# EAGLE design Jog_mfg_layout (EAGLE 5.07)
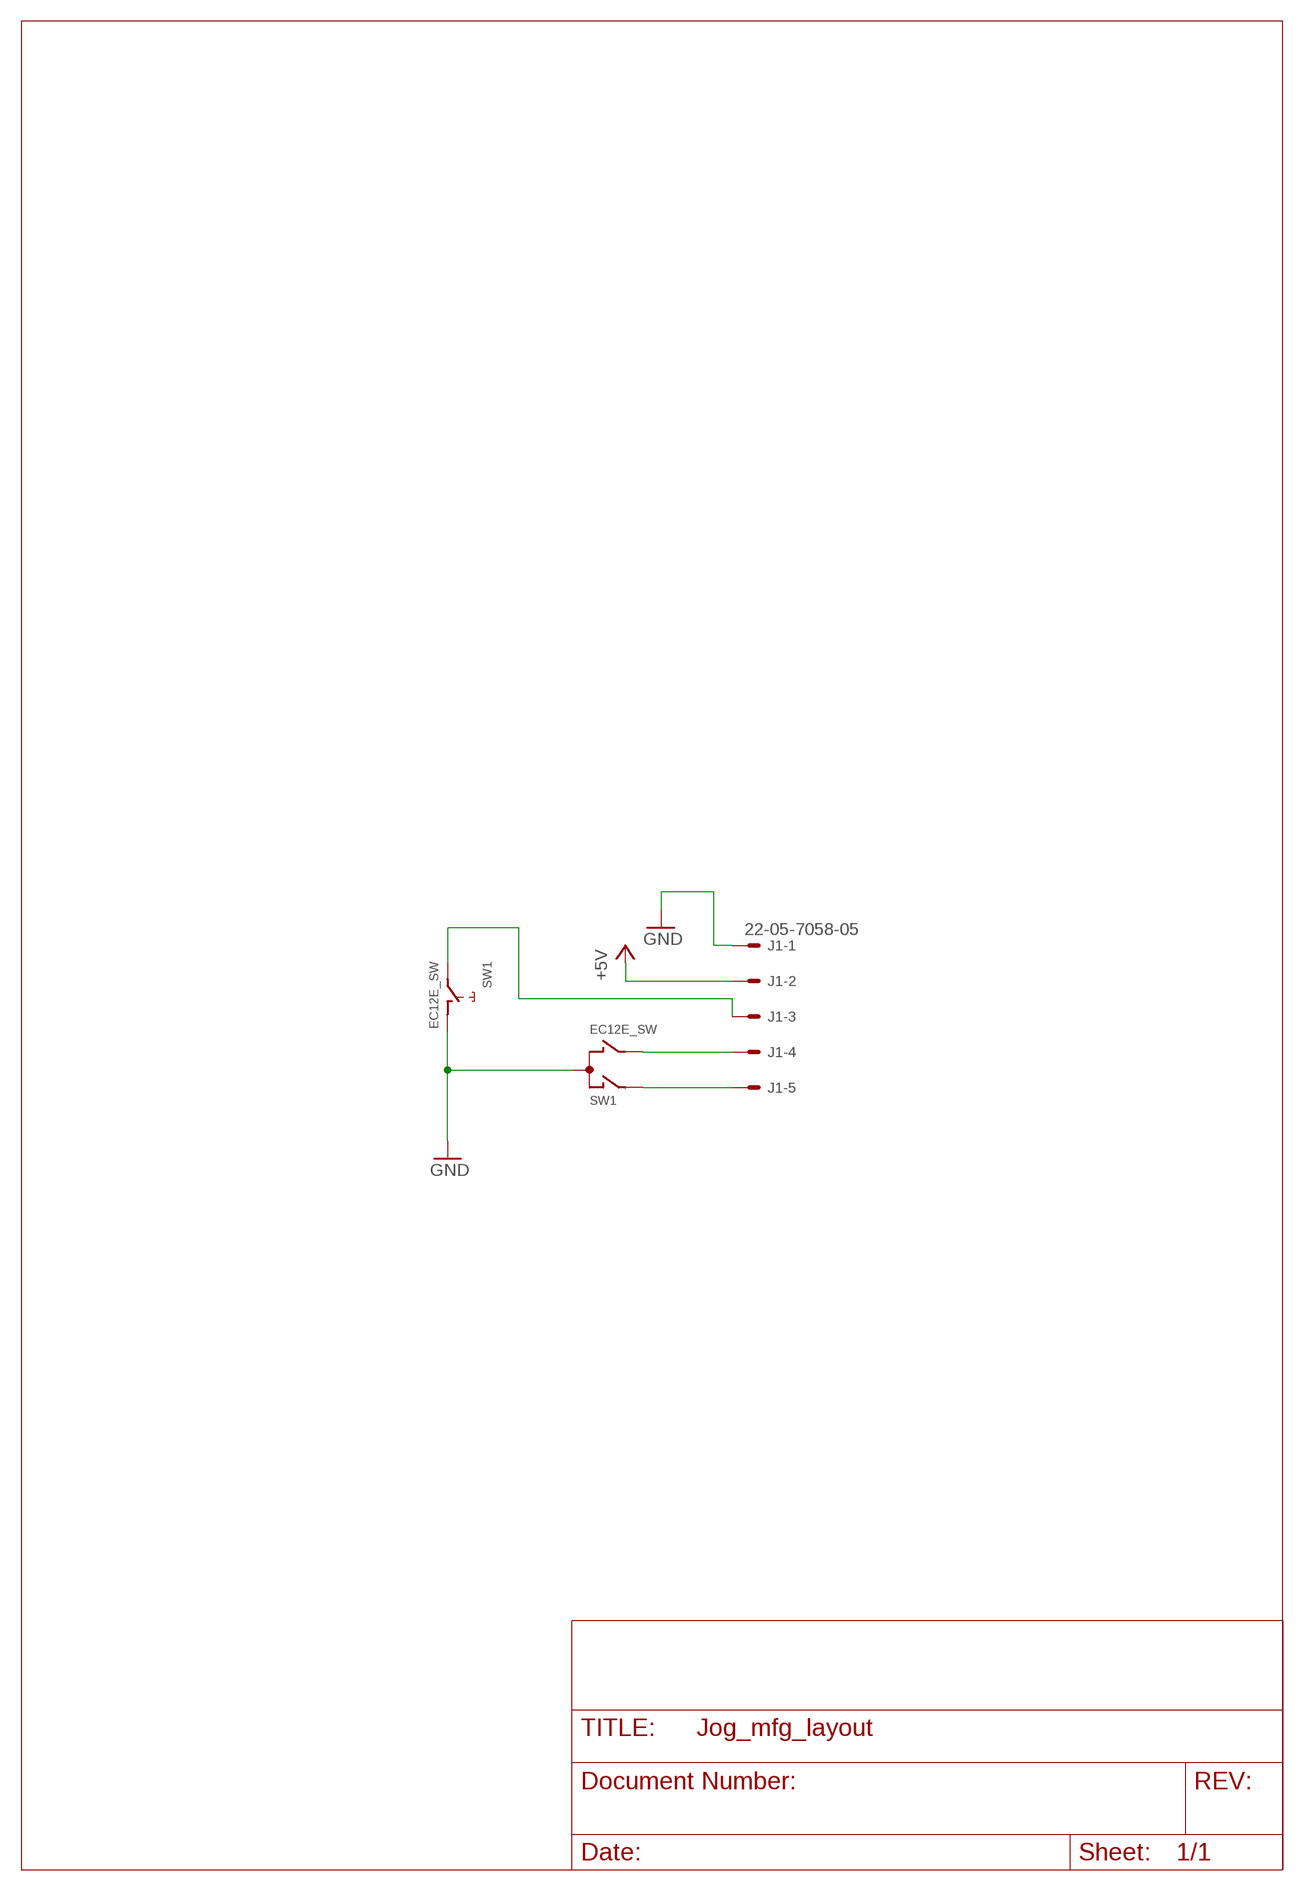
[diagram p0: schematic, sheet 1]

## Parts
J1  22-05-7058-05  [7395-05]
SW1  EC12E_SW  [ALPS_EC12E_SW]

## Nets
+5V: J1.2
GND: J1.1 SW1.C SW1.D
N$1: J1.5 SW1.A
N$2: J1.4 SW1.B
N$3: J1.3 SW1.E
Unconnected: SW1.GND1(G) SW1.GND2(G)

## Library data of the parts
J1 = con-molex:22-?-05: CONNECTOR wire to board 2.54 mm (.1 inch) pitch header
SW1 = switch-alps:EC12E_SW: ALPS rotary Encoder EC12E series with switch

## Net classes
0 default: width 1.27 mm, clearance 0.889 mm

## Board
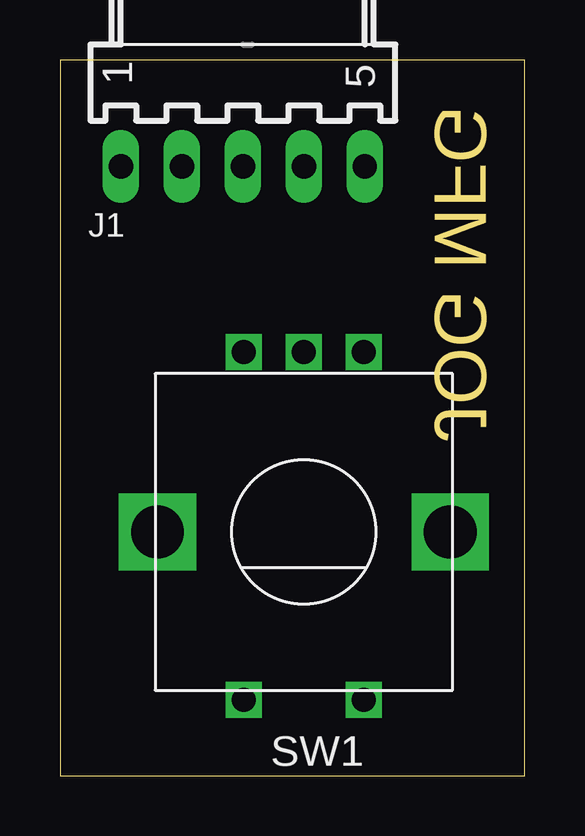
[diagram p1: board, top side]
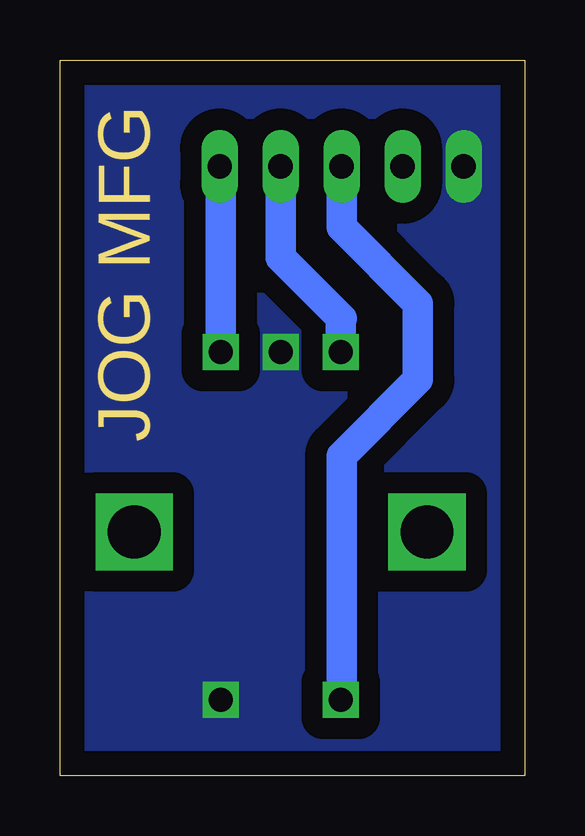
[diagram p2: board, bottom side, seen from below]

Size 19.36 x 29.84 mm. Coordinates in mm from the lower left corner, seen from the top.
Outline: 0,0 19.36,0 19.36,29.84 0,29.84 0,0
Copper layers (1*16): Top 0.035mm / dielectric 1.5mm / Bottom 0.035mm
Design rules "default": minimum track width 10mil, minimum drill 24mil, track to track 8mil, track to pad 8mil, pad to pad 8mil, via to via 8mil, smd to smd 8mil, copper to edge 40mil, drill to drill 8mil, minimum pad ring 10mil, minimum via ring 8mil, stop-mask expansion 4mil, vias tented up to drill 0mil, thermal gap 10mil

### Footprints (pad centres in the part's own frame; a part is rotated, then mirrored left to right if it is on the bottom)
7395-05 = drill 1.016 long: 1 5.08,0; 2 2.54,0; 3 0,0; 4 -2.54,0; 5 -5.08,0
ALPS_EC12E_SW = drill 1 square: A -2.5,-7.5; B 2.5,-7.5; C 0,-7.5; D -2.5,7; E 2.5,7 | drill 2.2 square: GND1 -6.1,0; GND2 6.1,0

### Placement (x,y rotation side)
J1  7.62,25.4 180 top
SW1  10.16,10.16 180 top

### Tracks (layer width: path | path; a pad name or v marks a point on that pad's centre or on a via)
GND
  pour Bottom (isolate 0.61, no thermals): 0,0 18.41,0 18.41,29.21 0,29.21
N$1
  Bottom 1.27: SW1.A 12.66,25.36 J1.5
N$2
  Bottom 1.27: SW1.B 7.66,19.01 7.62,19.05 10.16,21.59 J1.4
N$3
  Bottom 1.27: J1.3 7.62,22.86 4.45,19.68 4.45,16.51 7.62,13.34 7.62,3.2 SW1.E

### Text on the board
Milling: JOG MFG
